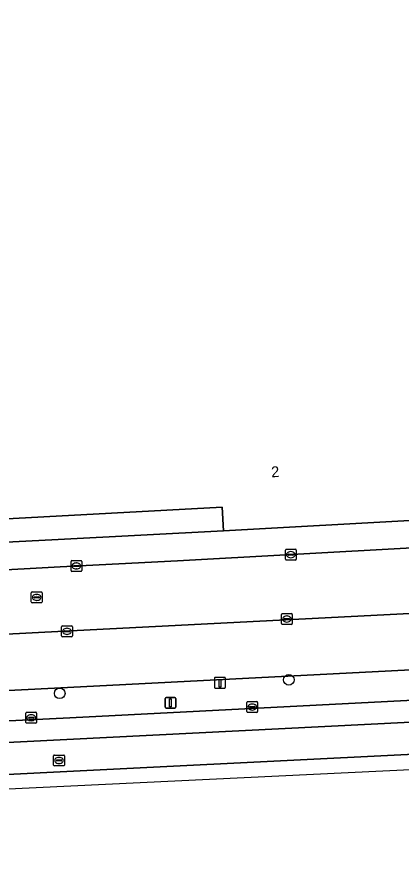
# Model space of a CAD drawing. Extents: x 161084 to 161928, y 385354 to 386522.
# Drawn here: x 161532.3 to 161567.8, y 385358.9 to 385436.6 of the extents above; entities that cross this region are included whole.
import ezdxf

# ---------------------------------------------------------------- set-up
doc = ezdxf.new("R2010")
doc.units = 0
for name, color, linetype in [('IMGEO_Berm_groen', 7, 'Continuous'), ('IMGEO_Boom', 7, 'Continuous'), ('IMGEO_Erf', 7, 'Continuous'), ('IMGEO_Kolk', 7, 'Continuous'), ('IMGEO_Laadpaal', 7, 'Continuous'), ('IMGEO_Lichtmast', 7, 'Continuous'), ('IMGEO_Pand', 7, 'Continuous'), ('IMGEO_Pand_nummerreeks', 7, 'Continuous'), ('IMGEO_Parkeervlak_open', 7, 'Continuous'), ('IMGEO_Rijbaan_lokaal_gesloten', 7, 'Continuous'), ('IMGEO_Rijbaan_lokaal_open', 7, 'Continuous'), ('IMGEO_Rioolput', 7, 'Continuous'), ('IMGEO_Voetpad_open', 7, 'Continuous')]:
    doc.layers.add(name, color=color, linetype=linetype)

msp = doc.modelspace()

# ---------------------------------------------------------------- linework, layer by layer
at = {"layer": 'IMGEO_Berm_groen'}
msp.add_lwpolyline([(161611.642, 385381.949), (161611.734, 385378.546), (161536.947, 385374.696), (161499.966, 385372.793), (161436.244, 385369.529), (161436.355, 385366.757), (161500.052, 385370.04), (161505.307, 385370.314), (161537.172, 385371.897), (161606.577, 385375.444)], dxfattribs=at)
at = {"layer": 'IMGEO_Boom'}
for centre in [(161557.385, 385375.395), (161536.24, 385374.145)]:
    msp.add_circle(centre, 0.489, dxfattribs=at)
at = {"layer": 'IMGEO_Erf'}
msp.add_lwpolyline([(161551.238, 385391.326), (161524.539, 385389.893), (161524.391, 385389.885), (161524.45, 385388.785), (161524.122, 385388.767), (161524.003, 385388.761), (161523.995, 385388.916), (161523, 385388.862), (161523.049, 385387.957), (161518.12, 385387.693), (161518.071, 385388.602), (161509.7, 385388.152), (161509.706, 385388.016), (161509.041, 385387.987), (161508.952, 385390.025), (161508.603, 385390.008), (161506.394, 385389.9), (161506.275, 385392.337), (161503.802, 385392.216), (161504.075, 385386.651), (161509.685, 385387), (161536.102, 385388.365), (161551.355, 385389.153)], close=True, dxfattribs=at)
at = {"layer": 'IMGEO_Kolk'}
for p, q in [((161557.075, 385386.527), (161557.075, 385387.379)), ((161557.15, 385387.453), (161558.002, 385387.453)), ((161557.563, 385387.233), (161557.588, 385387.233)), ((161558.076, 385387.379), (161558.076, 385386.527)), ((161537.357, 385386.411), (161538.209, 385386.411)), ((161558.002, 385386.453), (161557.15, 385386.453)), ((161557.334, 385386.947), (161557.334, 385386.959)), ((161557.772, 385386.91), (161557.374, 385386.91)), ((161557.377, 385386.996), (161557.775, 385386.996)), ((161557.586, 385386.673), (161557.561, 385386.673)), ((161557.818, 385386.959), (161557.818, 385386.947)), ((161537.282, 385385.485), (161537.282, 385386.337)), ((161537.541, 385385.905), (161537.541, 385385.917)), ((161537.979, 385385.868), (161537.581, 385385.868)), ((161537.584, 385385.954), (161537.982, 385385.954)), ((161537.793, 385385.631), (161537.768, 385385.631)), ((161537.77, 385386.191), (161537.795, 385386.191)), ((161538.025, 385385.917), (161538.025, 385385.905)), ((161538.283, 385386.337), (161538.283, 385385.485)), ((161538.209, 385385.411), (161537.357, 385385.411)), ((161556.707, 385380.588), (161556.707, 385381.44)), ((161556.782, 385381.514), (161557.634, 385381.514)), ((161556.966, 385381.008), (161556.966, 385381.02)), ((161557.404, 385380.971), (161557.006, 385380.971)), ((161557.009, 385381.057), (161557.407, 385381.057)), ((161557.195, 385381.294), (161557.22, 385381.294)), ((161557.45, 385381.02), (161557.45, 385381.008)), ((161557.708, 385381.44), (161557.708, 385380.588)), ((161536.413, 385379.448), (161536.413, 385380.3)), ((161536.488, 385380.374), (161537.34, 385380.374)), ((161537.414, 385380.3), (161537.414, 385379.448)), ((161557.634, 385380.514), (161556.782, 385380.514)), ((161557.218, 385380.734), (161557.193, 385380.734)), ((161536.672, 385379.868), (161536.672, 385379.88)), ((161537.11, 385379.831), (161536.712, 385379.831)), ((161536.715, 385379.917), (161537.113, 385379.917)), ((161536.924, 385379.594), (161536.899, 385379.594)), ((161536.901, 385380.154), (161536.926, 385380.154)), ((161537.156, 385379.88), (161537.156, 385379.868)), ((161537.34, 385379.374), (161536.488, 385379.374)), ((161553.508, 385372.455), (161553.508, 385373.307)), ((161553.583, 385373.381), (161554.435, 385373.381)), ((161554.509, 385373.307), (161554.509, 385372.455)), ((161553.767, 385372.875), (161553.767, 385372.887)), ((161554.205, 385372.838), (161553.807, 385372.838)), ((161553.81, 385372.924), (161554.208, 385372.924)), ((161554.019, 385372.601), (161553.994, 385372.601)), ((161553.996, 385373.161), (161554.021, 385373.161)), ((161554.251, 385372.887), (161554.251, 385372.875)), ((161533.106, 385371.466), (161533.106, 385372.318)), ((161533.181, 385372.392), (161534.033, 385372.392)), ((161533.365, 385371.886), (161533.365, 385371.898)), ((161533.803, 385371.849), (161533.405, 385371.849)), ((161533.408, 385371.935), (161533.806, 385371.935)), ((161533.594, 385372.172), (161533.619, 385372.172)), ((161533.849, 385371.898), (161533.849, 385371.886)), ((161534.107, 385372.318), (161534.107, 385371.466)), ((161554.435, 385372.381), (161553.583, 385372.381)), ((161534.033, 385371.392), (161533.181, 385371.392)), ((161533.617, 385371.612), (161533.592, 385371.612))]:
    msp.add_line(p, q, dxfattribs=at)
for points in [[(161557.075, 385386.527), (161557.075, 385387.379)], [(161557.15, 385387.453), (161558.002, 385387.453)], [(161558.076, 385387.379), (161558.076, 385386.527)], [(161537.357, 385386.411), (161538.209, 385386.411)], [(161558.002, 385386.453), (161557.15, 385386.453)], [(161537.282, 385385.485), (161537.282, 385386.337)], [(161538.283, 385386.337), (161538.283, 385385.485)], [(161538.209, 385385.411), (161537.357, 385385.411)], [(161556.707, 385380.588), (161556.707, 385381.44)], [(161556.782, 385381.514), (161557.634, 385381.514)], [(161557.708, 385381.44), (161557.708, 385380.588)], [(161536.413, 385379.448), (161536.413, 385380.3)], [(161536.488, 385380.374), (161537.34, 385380.374)], [(161537.414, 385380.3), (161537.414, 385379.448)], [(161557.634, 385380.514), (161556.782, 385380.514)], [(161537.34, 385379.374), (161536.488, 385379.374)], [(161553.508, 385372.455), (161553.508, 385373.307)], [(161553.583, 385373.381), (161554.435, 385373.381)], [(161554.509, 385373.307), (161554.509, 385372.455)], [(161533.106, 385371.466), (161533.106, 385372.318)], [(161533.181, 385372.392), (161534.033, 385372.392)], [(161534.107, 385372.318), (161534.107, 385371.466)], [(161554.435, 385372.381), (161553.583, 385372.381)], [(161534.033, 385371.392), (161533.181, 385371.392)]]:
    msp.add_lwpolyline(points, dxfattribs=at)
for centre, radius, start, end in [((161557.152, 385387.377), 0.0765, 91.55205, 178.44795), ((161557.152, 385387.377), 0.0765, 91.55205, 178.44795), ((161558, 385387.377), 0.0765, 1.55205, 88.44795), ((161558, 385387.377), 0.0765, 1.55205, 88.44795), ((161537.359, 385386.335), 0.0765, 91.55205, 178.44795), ((161537.359, 385386.335), 0.0765, 91.55205, 178.44795), ((161538.207, 385386.335), 0.0765, 1.55205, 88.44795), ((161538.207, 385386.335), 0.0765, 1.55205, 88.44795), ((161557.152, 385386.529), 0.0765, 181.55205, 268.44795), ((161557.152, 385386.529), 0.0765, 181.55205, 268.44795), ((161557.374, 385386.956), 0.0403, 85.87752, 175.75265), ((161557.371, 385386.946), 0.0366, 178.93798, 274.71019), ((161557.775, 385386.953), 0.043, 264.86636, 352.45326), ((161557.779, 385386.958), 0.0386, 1.73085, 96.63898), ((161558, 385386.529), 0.0765, 271.55205, 358.44795), ((161558, 385386.529), 0.0765, 271.55205, 358.44795), ((161537.581, 385385.914), 0.0403, 85.87752, 175.75265), ((161537.578, 385385.904), 0.0366, 178.93798, 274.71019), ((161537.982, 385385.911), 0.043, 264.86636, 352.45326), ((161537.986, 385385.916), 0.0386, 1.73085, 96.63898), ((161537.359, 385385.487), 0.0765, 181.55205, 268.44795), ((161537.359, 385385.487), 0.0765, 181.55205, 268.44795), ((161538.207, 385385.487), 0.0765, 271.55205, 358.44795), ((161538.207, 385385.487), 0.0765, 271.55205, 358.44795), ((161556.784, 385381.438), 0.0765, 91.55205, 178.44795), ((161556.784, 385381.438), 0.0765, 91.55205, 178.44795), ((161557.006, 385381.017), 0.0403, 85.87752, 175.75265), ((161557.003, 385381.007), 0.0366, 178.93798, 274.71019), ((161557.407, 385381.014), 0.043, 264.86636, 352.45326), ((161557.411, 385381.019), 0.0386, 1.73085, 96.63898), ((161557.632, 385381.438), 0.0765, 1.55205, 88.44795), ((161557.632, 385381.438), 0.0765, 1.55205, 88.44795), ((161536.49, 385380.298), 0.0765, 91.55205, 178.44795), ((161536.49, 385380.298), 0.0765, 91.55205, 178.44795), ((161537.338, 385380.298), 0.0765, 1.55205, 88.44795), ((161537.338, 385380.298), 0.0765, 1.55205, 88.44795), ((161556.784, 385380.59), 0.0765, 181.55205, 268.44795), ((161556.784, 385380.59), 0.0765, 181.55205, 268.44795), ((161557.632, 385380.59), 0.0765, 271.55205, 358.44795), ((161557.632, 385380.59), 0.0765, 271.55205, 358.44795), ((161536.49, 385379.45), 0.0765, 181.55205, 268.44795), ((161536.49, 385379.45), 0.0765, 181.55205, 268.44795), ((161536.712, 385379.877), 0.0403, 85.87752, 175.75265), ((161536.709, 385379.867), 0.0366, 178.93798, 274.71019), ((161537.113, 385379.874), 0.043, 264.86636, 352.45326), ((161537.117, 385379.879), 0.0386, 1.73085, 96.63898), ((161537.338, 385379.45), 0.0765, 271.55205, 358.44795), ((161537.338, 385379.45), 0.0765, 271.55205, 358.44795), ((161553.585, 385373.305), 0.0765, 91.55205, 178.44795), ((161553.585, 385373.305), 0.0765, 91.55205, 178.44795), ((161554.433, 385373.305), 0.0765, 1.55205, 88.44795), ((161554.433, 385373.305), 0.0765, 1.55205, 88.44795), ((161553.585, 385372.457), 0.0765, 181.55205, 268.44795), ((161553.585, 385372.457), 0.0765, 181.55205, 268.44795), ((161553.807, 385372.884), 0.0403, 85.87752, 175.75265), ((161553.804, 385372.874), 0.0366, 178.93798, 274.71019), ((161554.208, 385372.881), 0.043, 264.86636, 352.45326), ((161554.212, 385372.886), 0.0386, 1.73085, 96.63898), ((161554.433, 385372.457), 0.0765, 271.55205, 358.44795), ((161554.433, 385372.457), 0.0765, 271.55205, 358.44795), ((161533.183, 385372.316), 0.0765, 91.55205, 178.44795), ((161533.183, 385372.316), 0.0765, 91.55205, 178.44795), ((161533.405, 385371.895), 0.0403, 85.87752, 175.75265), ((161533.402, 385371.885), 0.0366, 178.93798, 274.71019), ((161533.806, 385371.892), 0.043, 264.86636, 352.45326), ((161533.81, 385371.897), 0.0386, 1.73085, 96.63898), ((161534.031, 385372.316), 0.0765, 1.55205, 88.44795), ((161534.031, 385372.316), 0.0765, 1.55205, 88.44795), ((161533.183, 385371.468), 0.0765, 181.55205, 268.44795), ((161533.183, 385371.468), 0.0765, 181.55205, 268.44795), ((161534.031, 385371.468), 0.0765, 271.55205, 358.44795), ((161534.031, 385371.468), 0.0765, 271.55205, 358.44795)]:
    msp.add_arc(centre, radius, start, end, dxfattribs=at)
for centre, major_axis, ratio, start_param, end_param in [((161557.562, 385386.953), (-0.387, 0.002), 0.722429, 4.712389, 7.853982), ((161557.587, 385386.953), (-0.39, 0.002), 0.717154, 1.570796, 4.712389), ((161537.769, 385385.911), (-0.387, 0.002), 0.722429, 4.712389, 7.853982), ((161537.794, 385385.911), (-0.39, 0.002), 0.717154, 1.570796, 4.712389), ((161557.194, 385381.014), (-0.387, 0.002), 0.722429, 4.712389, 7.853982), ((161557.219, 385381.014), (-0.39, 0.002), 0.717154, 1.570796, 4.712389), ((161536.9, 385379.874), (-0.387, 0.002), 0.722429, 4.712389, 7.853982), ((161536.925, 385379.874), (-0.39, 0.002), 0.717154, 1.570796, 4.712389), ((161553.995, 385372.881), (-0.387, 0.002), 0.722429, 4.712389, 7.853982), ((161554.02, 385372.881), (-0.39, 0.002), 0.717154, 1.570796, 4.712389), ((161533.593, 385371.892), (-0.387, 0.002), 0.722429, 4.712389, 7.853982), ((161533.618, 385371.892), (-0.39, 0.002), 0.717154, 1.570796, 4.712389)]:
    msp.add_ellipse(centre, major_axis=major_axis, ratio=ratio, start_param=start_param, end_param=end_param, dxfattribs=at)
at = {"layer": 'IMGEO_Laadpaal'}
for p, q in [((161550.53, 385375.538), (161550.53, 385374.697)), ((161550.53, 385375.538), (161550.53, 385374.697)), ((161551.446, 385375.622), (161550.605, 385375.622)), ((161551.446, 385375.622), (161550.605, 385375.622)), ((161551.53, 385374.706), (161551.53, 385375.547)), ((161551.53, 385374.706), (161551.53, 385375.547)), ((161550.614, 385374.622), (161551.455, 385374.622)), ((161550.614, 385374.622), (161551.455, 385374.622))]:
    msp.add_line(p, q, dxfattribs=at)
msp.add_lwpolyline([(161550.945, 385375.435), (161551.105, 385375.435), (161551.105, 385374.702), (161550.945, 385374.702), (161550.945, 385375.435)], dxfattribs=at)
for centre, start, end in [((161550.608, 385375.544), 92.4484, 184.28452), ((161550.608, 385375.544), 92.4484, 184.28452), ((161551.452, 385375.544), 2.4484, 94.28452), ((161551.452, 385375.544), 2.4484, 94.28452), ((161550.608, 385374.7), 182.4484, 274.28452), ((161550.608, 385374.7), 182.4484, 274.28452), ((161551.452, 385374.7), 272.4484, 4.28452), ((161551.452, 385374.7), 272.4484, 4.28452)]:
    msp.add_arc(centre, 0.0779, start, end, dxfattribs=at)
at = {"layer": 'IMGEO_Lichtmast'}
for p, q in [((161545.961, 385372.866), (161545.961, 385373.666)), ((161545.961, 385373.666), (161545.961, 385372.866)), ((161546.061, 385373.766), (161546.851, 385373.766)), ((161546.851, 385373.766), (161546.061, 385373.766)), ((161546.951, 385373.666), (161546.951, 385372.866)), ((161546.951, 385372.866), (161546.951, 385373.666)), ((161546.851, 385372.766), (161546.061, 385372.766)), ((161546.061, 385372.766), (161546.851, 385372.766))]:
    msp.add_line(p, q, dxfattribs=at)
msp.add_lwpolyline([(161546.381, 385373.641), (161546.531, 385373.641), (161546.531, 385372.891), (161546.381, 385372.891), (161546.381, 385373.641)], dxfattribs=at)
for centre, start, end in [((161546.061, 385373.666), 90, 180), ((161546.061, 385373.666), 90, 180), ((161546.851, 385373.666), 0, 90), ((161546.851, 385373.666), 360, 90), ((161546.061, 385372.866), 180, 270), ((161546.061, 385372.866), 180, 270), ((161546.851, 385372.866), 270, 0), ((161546.851, 385372.866), 270, 0)]:
    msp.add_arc(centre, 0.1, start, end, dxfattribs=at)
at = {"layer": 'IMGEO_Pand'}
msp.add_lwpolyline([(161586.302, 385424.825), (161585.195, 385447.291), (161585.171, 385447.778), (161584.754, 385447.756), (161575.301, 385447.248), (161530.941, 385444.868), (161530.957, 385444.578), (161531.457, 385435.246), (161527.076, 385435.01), (161527.577, 385425.67), (161523.129, 385425.432), (161523.637, 385415.955), (161522.896, 385415.916), (161524.122, 385388.767), (161524.45, 385388.785), (161524.391, 385389.885), (161524.539, 385389.893), (161551.238, 385391.326), (161551.355, 385389.153), (161587.959, 385391.187)], close=True, dxfattribs=at)
at = {"layer": 'IMGEO_Parkeervlak_open'}
for points in [[(161613.107, 385383.789), (161536.651, 385379.888), (161500, 385377.979), (161409.328, 385373.422), (161409.084, 385373.337)], [(161411.169, 385371.645), (161411.152, 385368.227), (161436.244, 385369.529), (161499.966, 385372.793), (161536.947, 385374.696), (161611.734, 385378.546)]]:
    msp.add_lwpolyline(points, dxfattribs=at)
at = {"layer": 'IMGEO_Rijbaan_lokaal_gesloten'}
msp.add_lwpolyline([(161508.768, 385368.474), (161604.686, 385373.29), (161611.842, 385373.703), (161615.993, 385374.116), (161622.181, 385375.572), (161612.776, 385375.763), (161606.577, 385375.444), (161537.172, 385371.897), (161505.307, 385370.314), (161500.052, 385370.04), (161436.355, 385366.757), (161401.799, 385364.905), (161400.42, 385364.894), (161400.333, 385364.8), (161381.454, 385363.768), (161381.262, 385363.858), (161323.951, 385361)], dxfattribs=at)
for points in [[(161625.701, 385371.623), (161625.454, 385376.07), (161622.465, 385375.567), (161622.181, 385375.572), (161615.993, 385374.116), (161611.842, 385373.703), (161604.686, 385373.29), (161508.768, 385368.474), (161402.097, 385363.009), (161402.264, 385360.078), (161479.217, 385364.029), (161505.666, 385365.356), (161523.978, 385366.275), (161544.274, 385367.294), (161580.676, 385369.12), (161602.822, 385370.279), (161621.627, 385370.918)], [(161402.333, 385358.921), (161450.189, 385361.402), (161611.523, 385369.168), (161621.627, 385370.918), (161602.822, 385370.279), (161580.676, 385369.12), (161544.274, 385367.294), (161523.978, 385366.275), (161505.666, 385365.356), (161479.217, 385364.029), (161402.264, 385360.078)]]:
    msp.add_lwpolyline(points, close=True, dxfattribs=at)
at = {"layer": 'IMGEO_Rijbaan_lokaal_open'}
for points in [[(161613.107, 385383.789), (161615.697, 385384.018), (161616.826, 385384.141), (161617.94, 385384.364), (161619.029, 385384.686), (161620.085, 385385.104), (161621.1, 385385.614), (161621.891, 385386.096), (161623.389, 385387.043), (161624.75, 385387.877), (161619.908, 385391.627), (161617.909, 385390.87), (161617.428, 385390.699), (161616.263, 385390.366), (161615.073, 385390.138), (161613.868, 385390.017), (161612.657, 385390.005), (161547.112, 385386.383), (161536.266, 385385.841), (161514.016, 385384.611), (161510.509, 385384.371)], [(161396.971, 385372.736), (161405.722, 385373.199), (161409.084, 385373.337), (161409.328, 385373.422), (161500, 385377.979), (161536.651, 385379.888), (161613.107, 385383.789)]]:
    msp.add_lwpolyline(points, dxfattribs=at)
at = {"layer": 'IMGEO_Rioolput'}
for p, q in [((161533.616, 385382.582), (161533.616, 385383.434)), ((161533.691, 385383.508), (161534.543, 385383.508)), ((161534.104, 385383.288), (161534.129, 385383.288)), ((161534.617, 385383.434), (161534.617, 385382.582)), ((161534.543, 385382.508), (161533.691, 385382.508)), ((161533.875, 385383.002), (161533.875, 385383.014)), ((161534.313, 385382.965), (161533.915, 385382.965)), ((161533.918, 385383.051), (161534.316, 385383.051)), ((161534.127, 385382.728), (161534.102, 385382.728)), ((161534.359, 385383.014), (161534.359, 385383.002)), ((161535.679, 385367.523), (161535.679, 385368.375)), ((161535.754, 385368.449), (161536.606, 385368.449)), ((161535.938, 385367.943), (161535.938, 385367.955)), ((161536.376, 385367.906), (161535.978, 385367.906)), ((161535.981, 385367.992), (161536.379, 385367.992)), ((161536.167, 385368.229), (161536.192, 385368.229)), ((161536.422, 385367.955), (161536.422, 385367.943)), ((161536.68, 385368.375), (161536.68, 385367.523)), ((161536.606, 385367.449), (161535.754, 385367.449)), ((161536.19, 385367.669), (161536.165, 385367.669))]:
    msp.add_line(p, q, dxfattribs=at)
for points in [[(161533.616, 385382.582), (161533.616, 385383.434)], [(161533.691, 385383.508), (161534.543, 385383.508)], [(161534.617, 385383.434), (161534.617, 385382.582)], [(161534.543, 385382.508), (161533.691, 385382.508)], [(161535.679, 385367.523), (161535.679, 385368.375)], [(161535.754, 385368.449), (161536.606, 385368.449)], [(161536.68, 385368.375), (161536.68, 385367.523)], [(161536.606, 385367.449), (161535.754, 385367.449)]]:
    msp.add_lwpolyline(points, dxfattribs=at)
for centre, radius, start, end in [((161533.693, 385383.432), 0.0765, 91.55205, 178.44795), ((161533.693, 385383.432), 0.0765, 91.55205, 178.44795), ((161534.541, 385383.432), 0.0765, 1.55205, 88.44795), ((161534.541, 385383.432), 0.0765, 1.55205, 88.44795), ((161533.693, 385382.584), 0.0765, 181.55205, 268.44795), ((161533.693, 385382.584), 0.0765, 181.55205, 268.44795), ((161533.915, 385383.011), 0.0403, 85.87752, 175.75265), ((161533.912, 385383.001), 0.0366, 178.93798, 274.71019), ((161534.316, 385383.008), 0.043, 264.86636, 352.45326), ((161534.32, 385383.013), 0.0386, 1.73085, 96.63898), ((161534.541, 385382.584), 0.0765, 271.55205, 358.44795), ((161534.541, 385382.584), 0.0765, 271.55205, 358.44795), ((161535.756, 385368.373), 0.0765, 91.55205, 178.44795), ((161535.756, 385368.373), 0.0765, 91.55205, 178.44795), ((161535.978, 385367.952), 0.0403, 85.87752, 175.75265), ((161535.975, 385367.942), 0.0366, 178.93798, 274.71019), ((161536.379, 385367.949), 0.043, 264.86636, 352.45326), ((161536.383, 385367.954), 0.0386, 1.73085, 96.63898), ((161536.604, 385368.373), 0.0765, 1.55205, 88.44795), ((161536.604, 385368.373), 0.0765, 1.55205, 88.44795), ((161535.756, 385367.525), 0.0765, 181.55205, 268.44795), ((161535.756, 385367.525), 0.0765, 181.55205, 268.44795), ((161536.604, 385367.525), 0.0765, 271.55205, 358.44795), ((161536.604, 385367.525), 0.0765, 271.55205, 358.44795)]:
    msp.add_arc(centre, radius, start, end, dxfattribs=at)
for centre, major_axis, ratio, start_param, end_param in [((161534.103, 385383.008), (-0.387, 0.002), 0.722429, 4.712389, 7.853982), ((161534.128, 385383.008), (-0.39, 0.002), 0.717154, 1.570796, 4.712389), ((161536.166, 385367.949), (-0.387, 0.002), 0.722429, 4.712389, 7.853982), ((161536.191, 385367.949), (-0.39, 0.002), 0.717154, 1.570796, 4.712389)]:
    msp.add_ellipse(centre, major_axis=major_axis, ratio=ratio, start_param=start_param, end_param=end_param, dxfattribs=at)
at = {"layer": 'IMGEO_Voetpad_open'}
for points in [[(161587.959, 385391.187), (161551.355, 385389.153), (161536.102, 385388.365), (161509.685, 385387), (161504.075, 385386.651), (161500, 385386.452), (161446.313, 385383.833), (161445.352, 385383.786), (161440.573, 385383.548), (161440.478, 385385.441), (161439.175, 385385.376), (161424.724, 385384.657), (161424.817, 385382.783), (161420.925, 385382.589), (161420.977, 385381.375), (161413.582, 385381.007), (161413.514, 385382.368), (161407.978, 385382.092), (161401.928, 385381.791), (161400.092, 385376.877), (161405.118, 385377.148)], [(161510.509, 385384.371), (161514.016, 385384.611), (161536.266, 385385.841), (161547.112, 385386.383), (161612.657, 385390.005)]]:
    msp.add_lwpolyline(points, dxfattribs=at)

# ---------------------------------------------------------------- texts
at = {"layer": 'IMGEO_Pand_nummerreeks'}
msp.add_text('2', height=1, rotation=3.07105, dxfattribs=at).set_placement((161555.786, 385394.094))

doc.saveas('drawing.dxf')
